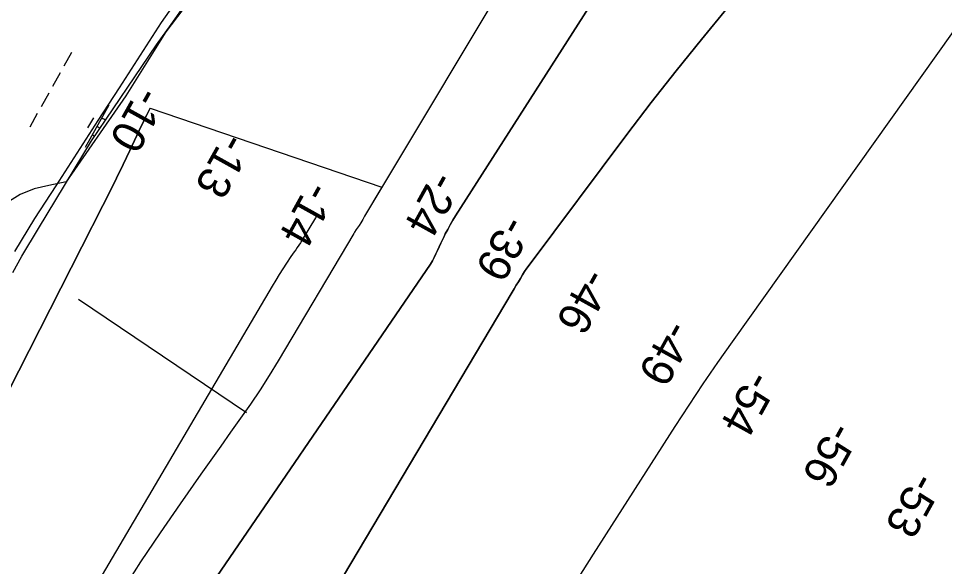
# Model space of a CAD drawing. Extents: x 3913936 to 3933962, y 195330 to 217741.
# Drawn here: x 3926148 to 3927100, y 208772 to 209336 of the extents above; entities that cross this region are included whole.
import ezdxf

# ---------------------------------------------------------------- set-up
doc = ezdxf.new("R2010")
doc.units = 0
for name, color, linetype in [('V-LEVE-TOET', 7, 'Continuous'), ('V-RIVR-EDGE', 7, 'Continuous'), ('V-RIVR-RANG', 7, 'Continuous'), ('V-RRAP-FSHR', 7, 'Continuous'), ('V-TOPO-DPTH', 7, 'Continuous'), ('V-TOPO-MAJR', 7, 'Continuous'), ('V-TOPO-MINR', 7, 'Continuous'), ('V-WETL-SWMP', 7, 'Continuous')]:
    doc.layers.add(name, color=color, linetype=linetype)

msp = doc.modelspace()

# ---------------------------------------------------------------- linework, layer by layer
at = {"layer": 'V-LEVE-TOET'}
msp.add_line((3926209.77, 209047.18), (3926382.62, 208930.61), dxfattribs=at)
at = {"layer": 'V-RIVR-EDGE'}
msp.add_lwpolyline([(3926329.25, 209361.03), (3926299.78, 209322.13), (3926258.53, 209256.12), (3926197.23, 209167.72), (3926179.55, 209164.18), (3926164.23, 209160.65), (3926150.08, 209154.75), (3926094.68, 209120.57)], dxfattribs=at)
at = {"layer": 'V-RRAP-FSHR'}
msp.add_lwpolyline([(3926144.53, 209096.38), (3926165.14, 209130.13), (3926186.84, 209163.74), (3926208.53, 209197.34), (3926230.22, 209230.95), (3926251.92, 209264.55), (3926273.61, 209298.16), (3926295.31, 209331.77), (3926318.1, 209364.69), (3926341.47, 209397.75), (3926364.94, 209429.46), (3926388.41, 209461.85), (3926412.27, 209493.96), (3926436.47, 209525.8), (3926461.82, 209556.74), (3926487.16, 209587.69), (3926506.32, 209622.52), (3926523.2, 209658.79), (3926542.21, 209693.94), (3926562.2, 209728.58), (3926583.45, 209762.45)], dxfattribs=at)
at = {"layer": 'V-TOPO-DPTH'}
for points in [[(3926277.78, 208418.87), (3926655.93, 209054.35), (3926658.04, 209057.89), (3926660.14, 209061.45), (3926662.23, 209065), (3926664.31, 209068.56), (3926666.45, 209072.08), (3926668.67, 209075.55), (3926671, 209078.95), (3926673.42, 209082.29), (3926773.76, 209216.38), (3926798.91, 209249.37), (3926824.44, 209282.07), (3926850.53, 209314.31), (3926877.01, 209346.25), (3926903.25, 209378.36), (3926928.79, 209411), (3926953.27, 209444.43), (3926977.06, 209478.4), (3927224.56, 209844.12)], [(3927224.56, 209844.12), (3926977.06, 209478.4), (3926953.27, 209444.43), (3926928.79, 209411), (3926903.25, 209378.36), (3926877.01, 209346.25), (3926850.53, 209314.31), (3926824.44, 209282.07), (3926798.91, 209249.37), (3926773.76, 209216.38), (3926673.42, 209082.29), (3926671, 209078.95), (3926668.67, 209075.55), (3926666.45, 209072.08), (3926664.31, 209068.56), (3926662.23, 209065), (3926660.14, 209061.45), (3926658.04, 209057.89), (3926655.93, 209054.35), (3926277.78, 208418.87)], [(3926836.88, 209687.66), (3926503.89, 209132.42), (3926502.25, 209129.15), (3926500.24, 209125.57), (3926498.53, 209122.79), (3926495.6, 209118.88), (3926493.75, 209116.2), (3926492.89, 209114.81), (3926415.2, 208983.78), (3926406.01, 208968.75), (3926396.57, 208953.88), (3926386.73, 208939.27), (3926376.63, 208924.83), (3926366.36, 208910.5), (3926356.11, 208896.16), (3926345.91, 208881.78), (3926335.73, 208867.38), (3926314.3, 208836.97), (3926293.76, 208807.14), (3926273.65, 208777.03), (3926254.2, 208746.48)], [(3926041.72, 208308.92), (3926571.84, 209083.15), (3926573.81, 209086.62), (3926575.69, 209090.13), (3926577.43, 209093.71), (3926579.08, 209097.34), (3926580.69, 209100.99), (3926582.35, 209104.62), (3926584.08, 209108.21), (3926585.85, 209111.79), (3926587.09, 209114.24), (3926589.58, 209118.99), (3926592.17, 209123.68), (3926594.9, 209128.29), (3926597.72, 209132.85), (3926929.91, 209652.17)], [(3926929.91, 209652.17), (3926597.72, 209132.85), (3926594.9, 209128.29), (3926592.17, 209123.68), (3926589.58, 209118.99), (3926587.09, 209114.24), (3926585.85, 209111.79), (3926584.08, 209108.21), (3926582.35, 209104.62), (3926580.69, 209100.99), (3926579.08, 209097.34), (3926577.43, 209093.71), (3926575.69, 209090.13), (3926573.81, 209086.62), (3926571.84, 209083.15), (3926041.72, 208308.92)], [(3925446.13, 207592.35), (3926234.96, 209143.49), (3926242.01, 209157.51), (3926248.98, 209171.58), (3926255.82, 209185.71), (3926262.57, 209199.88), (3926272.29, 209220.51), (3926274.13, 209224.39), (3926275.99, 209228.27), (3926277.87, 209232.15), (3926279.76, 209236.01), (3926283.56, 209243.73), (3926521.82, 209162.31)], [(3926521.82, 209162.31), (3926503.89, 209132.42), (3926502.25, 209129.15), (3926500.24, 209125.57), (3926498.53, 209122.79), (3926495.6, 209118.88), (3926493.75, 209116.2), (3926492.89, 209114.81), (3926415.2, 208983.78), (3926406.01, 208968.75), (3926396.57, 208953.88), (3926386.73, 208939.27), (3926376.63, 208924.83), (3926366.36, 208910.5), (3926356.11, 208896.16), (3926345.91, 208881.78), (3926335.73, 208867.38), (3926314.3, 208836.97), (3926293.76, 208807.14), (3926273.65, 208777.03), (3926254.2, 208746.48)]]:
    msp.add_lwpolyline(points, dxfattribs=at)
at = {"layer": 'V-TOPO-MAJR'}
msp.add_lwpolyline([(3927254.29, 209526.23), (3926882.04, 209003.51), (3926866.92, 208981.95), (3926852.02, 208960.24), (3926837.44, 208938.32), (3926823.08, 208916.25), (3926739.19, 208785.24), (3926683.57, 208697.24), (3926628.65, 208608.8), (3926574.78, 208519.72), (3926521.6, 208430.22), (3926340.51, 208121.24), (3926329.38, 208102), (3926318.37, 208082.7), (3926307.58, 208063.27), (3926296.91, 208043.77), (3925942.65, 207231.15), (3925917.38, 207177.27), (3925913.1, 207168.16), (3925908.81, 207159.05), (3925904.5, 207149.96), (3925900.17, 207140.87), (3925683.3, 206686.06)], dxfattribs=at)
at = {"layer": 'V-TOPO-MINR'}
for points in [[(3927224.56, 209844.12), (3926977.06, 209478.4), (3926953.27, 209444.43), (3926928.79, 209411), (3926903.25, 209378.36), (3926877.01, 209346.25), (3926850.53, 209314.31), (3926824.44, 209282.07), (3926798.91, 209249.37), (3926773.76, 209216.38), (3926673.42, 209082.29), (3926671, 209078.95), (3926668.67, 209075.55), (3926666.45, 209072.08), (3926664.31, 209068.56), (3926662.23, 209065), (3926660.14, 209061.45), (3926658.04, 209057.89), (3926655.93, 209054.35), (3926277.78, 208418.87)], [(3926836.88, 209687.66), (3926503.89, 209132.42), (3926502.25, 209129.15), (3926500.24, 209125.57), (3926498.53, 209122.79), (3926495.6, 209118.88), (3926493.75, 209116.2), (3926492.89, 209114.81), (3926415.2, 208983.78), (3926406.01, 208968.75), (3926396.57, 208953.88), (3926386.73, 208939.27), (3926376.63, 208924.83), (3926366.36, 208910.5), (3926356.11, 208896.16), (3926345.91, 208881.78), (3926335.73, 208867.38), (3926314.3, 208836.97), (3926293.76, 208807.14), (3926273.65, 208777.03), (3926254.2, 208746.48)], [(3926929.91, 209652.17), (3926597.72, 209132.85), (3926594.9, 209128.29), (3926592.17, 209123.68), (3926589.58, 209118.99), (3926587.09, 209114.24), (3926585.85, 209111.79), (3926584.08, 209108.21), (3926582.35, 209104.62), (3926580.69, 209100.99), (3926579.08, 209097.34), (3926577.43, 209093.71), (3926575.69, 209090.13), (3926573.81, 209086.62), (3926571.84, 209083.15), (3926041.72, 208308.92)], [(3926283.56, 209243.73), (3926279.76, 209236.01), (3926277.87, 209232.15), (3926275.99, 209228.27), (3926274.13, 209224.39), (3926272.29, 209220.51), (3926262.57, 209199.88), (3926255.82, 209185.71), (3926248.98, 209171.58), (3926242.01, 209157.51), (3926234.96, 209143.49), (3925446.13, 207592.35)], [(3926454.51, 209133.76), (3926454.51, 209132.51), (3926454.05, 209131.62), (3926453.61, 209130.97), (3926441.1, 209109.86), (3926439.62, 209107.44), (3926438.1, 209105.04), (3926436.51, 209102.69), (3926434.89, 209100.37), (3926433.24, 209098.05), (3926431.61, 209095.73), (3926430.01, 209093.39), (3926428.42, 209091.04), (3926423.86, 209084.19), (3926420.05, 209078.37), (3926416.31, 209072.52), (3926412.67, 209066.6), (3926409.09, 209060.64), (3925985.5, 208342.14)]]:
    msp.add_lwpolyline(points, dxfattribs=at)
at = {"layer": 'V-WETL-SWMP'}
for p, q in [((3926305.19, 209329.49), (3926320.06, 209350.59)), ((3926290.15, 209308.51), (3926305.19, 209329.49)), ((3926223.37, 209209.87), (3926290.15, 209308.51)), ((3926202.82, 209300.77), (3926194.98, 209286.82)), ((3926191.06, 209279.85), (3926183.22, 209265.9)), ((3926179.3, 209258.93), (3926171.46, 209244.98)), ((3926241.22, 209246.58), (3926216.72, 209202.99)), ((3926167.54, 209238.01), (3926159.69, 209224.06)), ((3926225.19, 209233.79), (3926219.31, 209223.33)), ((3926228.97, 209224.78), (3926232.23, 209222.95)), ((3926168.8, 209119.97), (3926223.37, 209209.87)), ((3926151.55, 209091.58), (3926168.8, 209119.97)), ((3926142.3, 209074.5), (3926151.55, 209091.58))]:
    msp.add_line(p, q, dxfattribs=at)
for centre, start, end in [((3926242.71, 209248.74), 239.88608, 255.03167), ((3926215.64, 209200.59), 52.01092, 61.42973)]:
    msp.add_arc(centre, 17.62, start, end, dxfattribs=at)

# ---------------------------------------------------------------- texts
at = {"layer": 'V-RIVR-RANG'}
for s, rotation, p in [('-10', 240.87833, (3926272.4, 209267.69)), ('-13', 240.87833, (3926360.46, 209220.28)), ('-24', 241.02103, (3926575.68, 209180.85)), ('-14', 240.87833, (3926447.1, 209170.33)), ('-39', 241.02103, (3926648.53, 209135.35)), ('-46', 241.02103, (3926731.76, 209080.99)), ('-49', 241.02103, (3926816.1, 209027.81)), ('-54', 241.02103, (3926900.84, 208975.76)), ('-56', 241.02103, (3926984.79, 208923.13)), ('-53', 241.02103, (3927070.05, 208871.38))]:
    msp.add_text(s, height=33.5, rotation=rotation, dxfattribs=at).set_placement(p)

doc.saveas('drawing.dxf')
